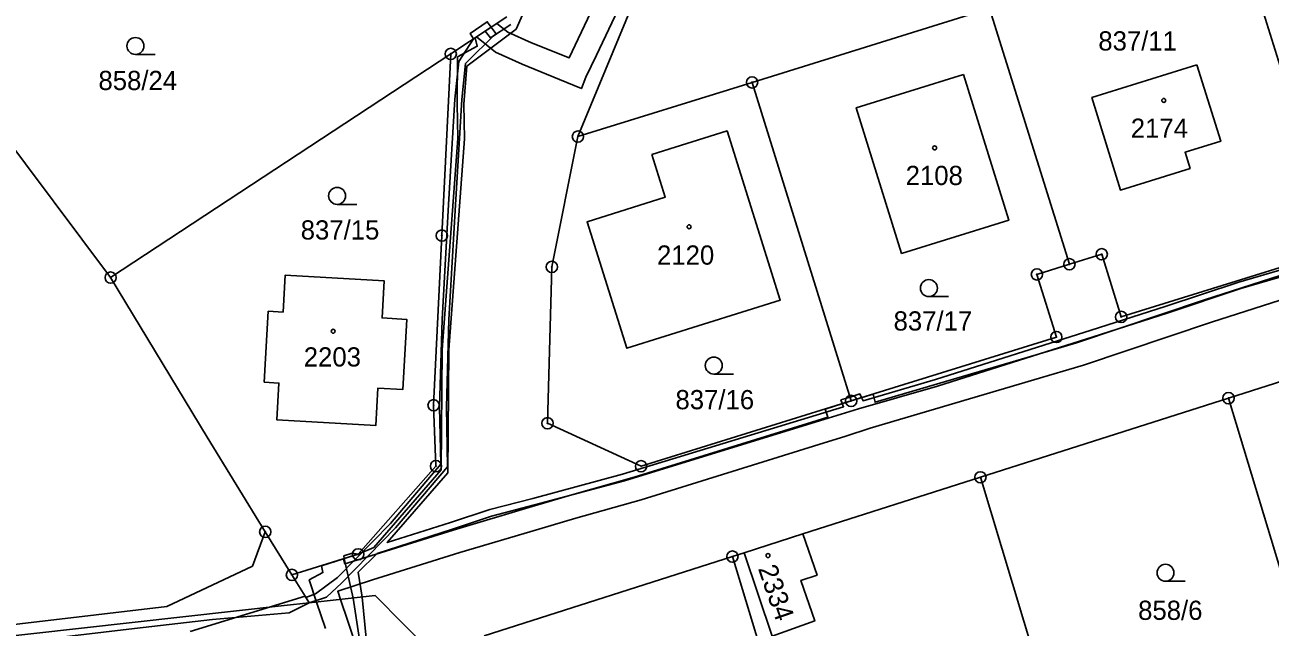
# Model space of a CAD drawing. Extents: x -680203 to -673936, y -1102717 to -1093650.
# Drawn here: x -679233.9 to -679123.8, y -1097519.2 to -1097465.9 of the extents above; entities that cross this region are included whole.
import ezdxf

# ---------------------------------------------------------------- set-up
doc = ezdxf.new("R2010")
doc.units = 0
for name, color, linetype in [('SOxx02xx_Koleje_param další_Popis10', 7, 'Continuous'), ('SOxxxxxx_Koleje_hlavní_body_Popis10', 7, 'Continuous'), ('SOxxxxxx_Koleje_LN_parametry_Popis10', 7, 'Continuous'), ('SOxxxxxx_Koleje_param další_Popis10', 7, 'Continuous'), ('SOxxxxxx_Osa_bod_P', 7, 'Continuous'), ('x_prac', 7, 'Continuous')]:
    doc.layers.add(name, color=color, linetype=linetype)

msp = doc.modelspace()

# ---------------------------------------------------------------- linework, layer by layer
at = {"layer": 'SOxx02xx_Koleje_param další_Popis10'}
for centre, radius in [((-679196.27, -1097468.46), 0.5), ((-679196.27, -1097468.46), 0.0303), ((-679169.63, -1097470.98), 0.5), ((-679169.63, -1097470.98), 0.0303), ((-679185.02, -1097475.77), 0.5), ((-679185.02, -1097475.77), 0.0303), ((-679197.05, -1097484.53), 0.5), ((-679197.05, -1097484.53), 0.0303), ((-679141.58, -1097487.07), 0.5), ((-679138.72, -1097486.18), 0.5), ((-679138.72, -1097486.18), 0.0303), ((-679226.33, -1097488.25), 0.5), ((-679187.33, -1097487.3), 0.5), ((-679187.33, -1097487.3), 0.0303), ((-679144.45, -1097487.96), 0.5), ((-679141.58, -1097487.07), 0.0303), ((-679226.33, -1097488.25), 0.0303), ((-679144.45, -1097487.96), 0.0303), ((-679137, -1097491.72), 0.5), ((-679137, -1097491.72), 0.0303), ((-679142.73, -1097493.5), 0.5), ((-679142.73, -1097493.5), 0.0303), ((-679160.87, -1097499.15), 0.5), ((-679127.51, -1097498.91), 0.5), ((-679197.78, -1097499.54), 0.5), ((-679197.78, -1097499.54), 0.0303), ((-679160.87, -1097499.15), 0.0303), ((-679127.51, -1097498.91), 0.0303), ((-679187.71, -1097501.13), 0.5), ((-679187.71, -1097501.13), 0.0303), ((-679197.57, -1097504.92), 0.5), ((-679197.57, -1097504.92), 0.0303), ((-679179.44, -1097504.93), 0.5), ((-679179.44, -1097504.93), 0.0303), ((-679149.44, -1097505.91), 0.5), ((-679149.44, -1097505.91), 0.0303), ((-679212.66, -1097510.73), 0.5), ((-679212.66, -1097510.73), 0.0303), ((-679204.45, -1097512.72), 0.5), ((-679204.45, -1097512.72), 0.0303), ((-679171.37, -1097512.92), 0.5), ((-679171.37, -1097512.92), 0.0303), ((-679210.31, -1097514.54), 0.5), ((-679210.31, -1097514.54), 0.0303)]:
    msp.add_circle(centre, radius, dxfattribs=at)
at = {"layer": 'SOxxxxxx_Koleje_hlavní_body_Popis10'}
for p, q in [((-679224.14, -1097468.51), (-679222.39, -1097468.51)), ((-679206.31, -1097481.77), (-679204.56, -1097481.77)), ((-679154, -1097489.92), (-679152.25, -1097489.92)), ((-679173.01, -1097496.78), (-679171.26, -1097496.78)), ((-679133.08, -1097515.1), (-679131.33, -1097515.1))]:
    msp.add_line(p, q, dxfattribs=at)
for centre in [(-679224.14, -1097467.76), (-679206.31, -1097481.02), (-679154, -1097489.17), (-679173.01, -1097496.03), (-679133.08, -1097514.35)]:
    msp.add_circle(centre, 0.75, dxfattribs=at)
at = {"layer": 'SOxxxxxx_Koleje_LN_parametry_Popis10'}
for points in [[(-679118.55, -1097486.29), (-679126.61, -1097488.64), (-679133.12, -1097490.8), (-679139.66, -1097492.9), (-679153.42, -1097497.26), (-679159.82, -1097499.13), (-679159.95, -1097498.86), (-679160.87, -1097499.15), (-679161.65, -1097499.39), (-679161.54, -1097499.67), (-679181.08, -1097505.64), (-679189.02, -1097507.77), (-679192.81, -1097508.77), (-679196.3, -1097509.91), (-679201.88, -1097511.68), (-679196.52, -1097505.5), (-679196.43, -1097494.64), (-679195.05, -1097475.96), (-679195.11, -1097472.9), (-679194.83, -1097469.54), (-679190.47, -1097466.26), (-679185.92, -1097455.91)], [(-679181.13, -1097458.96), (-679185.27, -1097467.7), (-679185.8, -1097468.82), (-679189.14, -1097467.49), (-679191.22, -1097466.54), (-679192.19, -1097465.77), (-679193.98, -1097466.95), (-679192.3, -1097468.3), (-679189.94, -1097469.37), (-679186.64, -1097470.73), (-679184.72, -1097471.53), (-679184.31, -1097470.53), (-679183.39, -1097468.58), (-679179.31, -1097459.96)], [(-679190.95, -1097465.86), (-679192.76, -1097467.05), (-679193.22, -1097466.46), (-679194.1, -1097467.03), (-679193.92, -1097467.79), (-679195.68, -1097468.72), (-679195.71, -1097472.88), (-679195.65, -1097475.94), (-679197.03, -1097494.62), (-679197.12, -1097505.26), (-679203.06, -1097512.11), (-679204.45, -1097512.72), (-679205.68, -1097513.1), (-679204.89, -1097516.59), (-679204.32, -1097520.25)], [(-679203.73, -1097520.13), (-679204.09, -1097516.5), (-679204.46, -1097514.3), (-679202.76, -1097512.65), (-679196.12, -1097510.48), (-679192.65, -1097509.35), (-679188.86, -1097508.35), (-679180.92, -1097506.22), (-679160.22, -1097499.86), (-679153.24, -1097497.84), (-679139.48, -1097493.48), (-679132.94, -1097491.38), (-679126.43, -1097489.22), (-679117.61, -1097486.63)], [(-679122.11, -1097487.8), (-679129.64, -1097490.22), (-679140.95, -1097494.02), (-679145.31, -1097495.3), (-679158.76, -1097499.27), (-679158.93, -1097498.55), (-679160.87, -1097499.15), (-679163.17, -1097499.87), (-679162.94, -1097500.59), (-679164.34, -1097501.03), (-679180.04, -1097505.9), (-679185.78, -1097507.53), (-679189.08, -1097508.5), (-679196.05, -1097510.57), (-679203.8, -1097512.99), (-679205.64, -1097513.56), (-679205.74, -1097513.12), (-679207.7, -1097513.73), (-679207.56, -1097514.33), (-679208.78, -1097514.99), (-679208.13, -1097516.95), (-679207.35, -1097519.29)], [(-679204.54, -1097521.14), (-679205.37, -1097518.63), (-679206.01, -1097516.71), (-679206.26, -1097515.99), (-679203.18, -1097514.97), (-679195.45, -1097512.57), (-679188.48, -1097510.5), (-679185.2, -1097509.53), (-679179.44, -1097507.9), (-679163.72, -1097503.01), (-679161.33, -1097502.27), (-679159.2, -1097501.56), (-679144.73, -1097497.3), (-679140.33, -1097496), (-679129, -1097492.2), (-679121.47, -1097489.78)]]:
    msp.add_lwpolyline(points, dxfattribs=at)
for points in [[(-679194.25, -1097467.13), (-679192.69, -1097466.1), (-679193.04, -1097465.61), (-679194.55, -1097466.66)], [(-679208.78, -1097517.02), (-679207.25, -1097516.5), (-679205.88, -1097515.23), (-679201.15, -1097510.39), (-679196.55, -1097504.97), (-679196.65, -1097499.7), (-679196.43, -1097491.96), (-679195.85, -1097481.81), (-679195.29, -1097472.5), (-679194.97, -1097469.32), (-679192.29, -1097466.66), (-679192.69, -1097466.1), (-679194.25, -1097467.13), (-679195.55, -1097469.12), (-679195.89, -1097472.46), (-679196.45, -1097481.77), (-679197.03, -1097491.94), (-679197.25, -1097499.7), (-679197.15, -1097504.75), (-679201.59, -1097509.99), (-679206.28, -1097514.77), (-679208.22, -1097516.21), (-679209.08, -1097516.54)], [(-679161.77, -1097499.06), (-679161.65, -1097499.39), (-679160.87, -1097499.15), (-679159.95, -1097498.86), (-679160.1, -1097498.54), (-679160.97, -1097498.81)], [(-679205.73, -1097512.86), (-679205.68, -1097513.1), (-679204.45, -1097512.72), (-679204.99, -1097512.62)], [(-679262.37, -1097522.6), (-679263.09, -1097522.65), (-679262.92, -1097523.73), (-679251.15, -1097522.37), (-679237.95, -1097520.91), (-679224.23, -1097519.27), (-679217.34, -1097518.47), (-679210.55, -1097517.89), (-679208.78, -1097517.02), (-679210.98, -1097517.26), (-679255.56, -1097522.22)]]:
    msp.add_lwpolyline(points, close=True, dxfattribs=at)
at = {"layer": 'SOxxxxxx_Koleje_param další_Popis10'}
for centre in [(-679133.23, -1097472.58), (-679153.49, -1097476.77), (-679175.19, -1097483.75), (-679206.66, -1097492.99), (-679168.22, -1097512.83)]:
    msp.add_circle(centre, 0.175, dxfattribs=at)
at = {"layer": 'x_prac'}
for p, q in [((-679126.66, -1097457.61), (-679117.9, -1097485.78)), ((-679169.63, -1097470.98), (-679148.63, -1097464.45)), ((-679148.63, -1097464.45), (-679141.58, -1097487.07)), ((-679196.27, -1097468.46), (-679191.3, -1097465.19)), ((-679241.48, -1097468.02), (-679226.33, -1097488.25)), ((-679226.33, -1097488.25), (-679196.27, -1097468.46)), ((-679185.02, -1097475.77), (-679169.63, -1097470.98)), ((-679160.87, -1097499.15), (-679169.63, -1097470.98)), ((-679105.63, -1097491.91), (-679127.51, -1097498.91)), ((-679127.51, -1097498.91), (-679149.44, -1097505.91)), ((-679115.21, -1097539.66), (-679127.51, -1097498.91)), ((-679165.13, -1097510.92), (-679149.44, -1097505.91)), ((-679137.23, -1097546.27), (-679149.44, -1097505.91)), ((-679213.8, -1097513.77), (-679212.66, -1097510.73)), ((-679212.66, -1097510.73), (-679210.31, -1097514.54)), ((-679170.33, -1097512.59), (-679165.13, -1097510.92)), ((-679204.45, -1097512.72), (-679210.31, -1097514.54)), ((-679193.3, -1097519.93), (-679171.37, -1097512.92)), ((-679171.37, -1097512.92), (-679170.33, -1097512.59)), ((-679159.24, -1097552.88), (-679171.37, -1097512.92)), ((-679210.31, -1097514.54), (-679209.15, -1097516.42)), ((-679209.15, -1097516.42), (-679219.3, -1097519.55)), ((-679197.95, -1097521.42), (-679202.94, -1097516.37))]:
    msp.add_line(p, q, dxfattribs=at)
for points in [[(-679154.61, -1097433.85), (-679167.9, -1097445.21), (-679178.35, -1097459.62), (-679185.02, -1097475.77)], [(-679196.27, -1097468.46), (-679197.05, -1097484.53), (-679197.78, -1097499.54), (-679197.57, -1097504.92), (-679204.45, -1097512.72)], [(-679130.31, -1097469.43), (-679128.2, -1097476.18), (-679131.35, -1097477.16), (-679130.91, -1097478.59), (-679137.06, -1097480.5), (-679139.59, -1097472.32), (-679130.31, -1097469.43)], [(-679150.95, -1097470.29), (-679146.94, -1097483.17), (-679156.41, -1097486.11), (-679160.42, -1097473.23), (-679150.95, -1097470.29)], [(-679178.49, -1097477.35), (-679171.83, -1097475.27), (-679167.14, -1097490.25), (-679180.71, -1097494.5), (-679184.21, -1097483.31), (-679177.3, -1097481.14), (-679178.49, -1097477.35)], [(-679185.02, -1097475.77), (-679187.33, -1097487.3), (-679187.71, -1097501.13), (-679179.44, -1097504.93), (-679160.87, -1097499.15)], [(-679141.58, -1097487.07), (-679138.72, -1097486.18), (-679137, -1097491.72), (-679117.9, -1097485.78)], [(-679160.87, -1097499.15), (-679142.73, -1097493.5), (-679144.45, -1097487.96), (-679141.58, -1097487.07)], [(-679212.66, -1097510.73), (-679217.81, -1097502.37), (-679226.33, -1097488.25)], [(-679212.76, -1097497.5), (-679212.4, -1097491.22), (-679211.09, -1097491.3), (-679210.9, -1097488.02), (-679202.16, -1097488.53), (-679202.33, -1097491.81), (-679200.16, -1097491.95), (-679200.5, -1097498.13), (-679202.71, -1097498.01), (-679202.89, -1097501.33), (-679211.65, -1097500.82), (-679211.46, -1097497.57), (-679212.76, -1097497.5)], [(-679165.13, -1097510.92), (-679163.88, -1097514.56), (-679165.31, -1097515.03), (-679164.08, -1097518.61), (-679167.85, -1097519.95), (-679170.33, -1097512.59)], [(-679262.23, -1097522.14), (-679240.64, -1097519.59), (-679221.35, -1097517.33), (-679213.8, -1097513.77)], [(-679202.94, -1097516.37), (-679208.78, -1097517.02), (-679209.15, -1097516.42)]]:
    msp.add_lwpolyline(points, dxfattribs=at)

# ---------------------------------------------------------------- texts
at = {"layer": 'SOxxxxxx_Osa_bod_P'}
for s, p in [('837/11', (-679139.02, -1097468.16)), ('858/24', (-679227.41, -1097471.66)), ('2174', (-679136.15, -1097475.88)), ('2108', (-679156.05, -1097480.06)), ('837/15', (-679209.53, -1097484.88)), ('2120', (-679178.03, -1097487.1)), ('837/17', (-679157.12, -1097492.93)), ('2203', (-679209.26, -1097496.11)), ('837/16', (-679176.4, -1097499.89)), ('858/6', (-679135.5, -1097518.52))]:
    msp.add_text(s, height=1.7, dxfattribs=at).set_placement(p)
msp.add_text('2334', height=1.7, rotation=289, dxfattribs=at).set_placement((-679169.12, -1097513.97))

doc.saveas('drawing.dxf')
